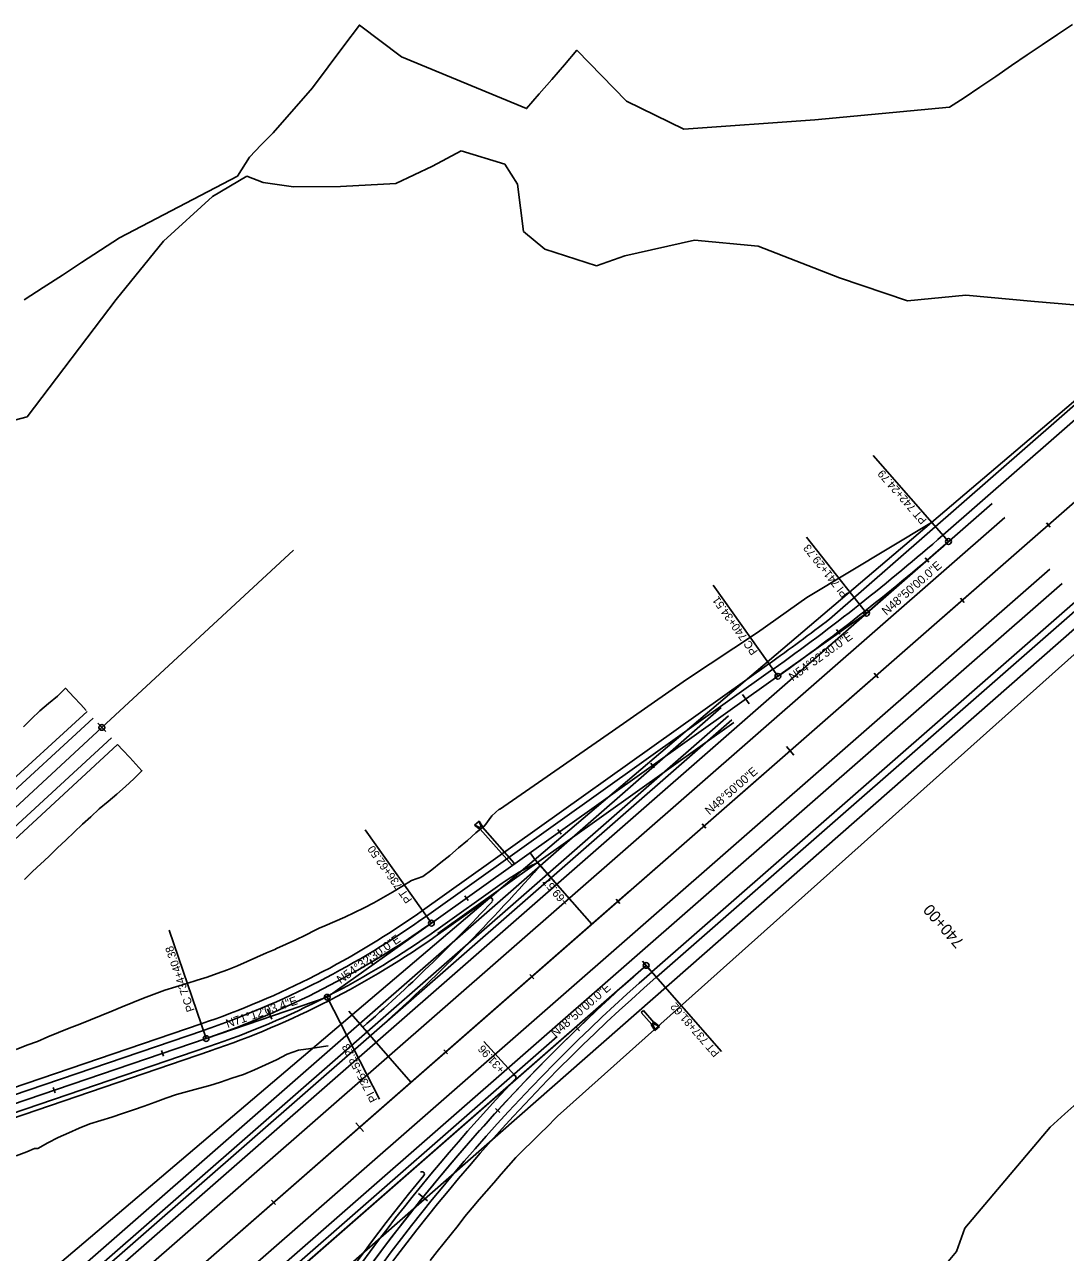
# Model space of a CAD drawing. Extents: x 1300404 to 1323571, y 234004 to 252077.
# Drawn here: x 1311522 to 1312432, y 241789 to 242863 of the extents above; entities that cross this region are included whole.
import ezdxf

# ---------------------------------------------------------------- set-up
doc = ezdxf.new("R2010")
doc.units = 0
for name, color, linetype in [('R_Const Limits', 7, 'Continuous'), ('R_Draft', 7, 'Continuous'), ('R_Flooplain', 7, 'Continuous'), ('R_Horz Alg Annot', 7, 'Continuous'), ('R_Horz Alg Annot Leader', 7, 'Continuous'), ('R_Horz Alg Major Ticks', 7, 'Continuous'), ('R_Horz Alg Minor Ticks', 7, 'Continuous'), ('R_Horz Alg Station Annot', 7, 'Continuous'), ('R_Horz Alg Tangents', 7, 'Continuous'), ('R_Horz Alg Tangents Text', 7, 'Continuous'), ('R_Information', 7, 'Continuous'), ('R_Lane Edge', 7, 'Continuous'), ('R_Pipe Culvert', 7, 'Continuous'), ('R_Proposed', 7, 'Continuous'), ('R_Shoulder', 7, 'Continuous')]:
    doc.layers.add(name, color=color, linetype=linetype)

msp = doc.modelspace()

# ---------------------------------------------------------------- linework, layer by layer
at = {"layer": 'R_Const Limits'}
for points in [[(1312438.5, 242863.3), (1312425.3, 242854.5), (1312412.1, 242845.7), (1312398.9, 242836.9), (1312385.2, 242827.4), (1312371.4, 242818), (1312357.6, 242808.6), (1312343.9, 242799.2), (1312331, 242791), (1312213.2, 242780), (1312098.6, 242771.9), (1312048.4, 242796.3), (1312005.2, 242840.8), (1311994.2, 242828.1), (1311983.2, 242815.4), (1311972.2, 242802.6), (1311961.2, 242789.9), (1311851.8, 242835.1), (1311814.9, 242862.8), (1311801.3, 242844.6), (1311787.6, 242826.3), (1311773.9, 242808), (1311739.5, 242768.5), (1311729.1, 242758), (1311718.8, 242747.4), (1311708.3, 242730.7), (1311605.1, 242676.9), (1311588.4, 242666), (1311571.8, 242655.1), (1311555.2, 242644.2), (1311538.5, 242633.4), (1311521.9, 242622.5)], [(1311514.8, 241966.8), (1311524, 241970.6), (1311533.4, 241973.9), (1311542.6, 241977.9), (1311551.9, 241981.8), (1311561.2, 241985.5), (1311570.5, 241989.1), (1311579.8, 241992.8), (1311589.1, 241996.6), (1311598.4, 242000.3), (1311607.6, 242004.2), (1311616.9, 242008.1), (1311626.2, 242011.7), (1311635.6, 242015.2), (1311644.9, 242018.9), (1311654.5, 242021.8), (1311664.1, 242024.6), (1311673, 242027.4), (1311681.9, 242030.3), (1311690.7, 242033.4), (1311699.5, 242036.7), (1311708.2, 242040.2), (1311716.7, 242043.8), (1311725.3, 242047.7), (1311733.8, 242051.5), (1311741.1, 242054.5), (1311742.4, 242055.1), (1311751, 242058.9), (1311759.4, 242062.9), (1311767.8, 242067), (1311776.2, 242071.2), (1311779.8, 242073.1), (1311784.8, 242075.1), (1311793.5, 242078.8), (1311802.1, 242082.6), (1311810.7, 242086.7), (1311819.1, 242090.9), (1311827.5, 242095.3), (1311835.8, 242099.9), (1311844, 242104.6), (1311852.1, 242109.5), (1311860.6, 242114.7), (1311870.4, 242118.2), (1311878.4, 242124.1), (1311886.2, 242130.4), (1311894, 242136.7), (1311901.7, 242143.2), (1311909.4, 242149.6), (1311916.8, 242156.3), (1311924.6, 242162.7), (1311930.8, 242171.3), (1311937.2, 242177.2), (1311937.4, 242176.9), (1311971.5, 242200.5), (1312036.2, 242245.4), (1312100.9, 242290.4), (1312163, 242331.7), (1312206.3, 242362.3), (1312315.2, 242427.9), (1312325.2, 242416.8)], [(1312524.9, 242388.2), (1311988.1, 241908.5), (1311986.5, 241906.8), (1311979.6, 241899.9), (1311972.6, 241893.1), (1311965.7, 241886.2), (1311958.7, 241879.3), (1311951.8, 241872.4), (1311945.3, 241865.2), (1311938.9, 241857.8), (1311932.5, 241850.4), (1311926.1, 241843.1), (1311919.7, 241835.7), (1311913.4, 241828.3), (1311907.2, 241820.7), (1311901.3, 241812.9), (1311895.1, 241805.4), (1311889, 241797.7), (1311882.9, 241790.1), (1311876.9, 241782.5)], [(1311521.1, 242249.1), (1311528.1, 242256.2), (1311535.4, 242263.1), (1311543.2, 242269.4), (1311550.9, 242275.8), (1311558, 242282.9), (1311565.3, 242275), (1311571.2, 242268.6), (1311576.1, 242263.3)], [(1311603.5, 242233.7), (1311608.2, 242228.6), (1311614.2, 242222.2), (1311624.8, 242210.7), (1311617.6, 242203.7), (1311610.3, 242196.9), (1311602.8, 242190.3), (1311595.3, 242183.7), (1311587.4, 242177.5), (1311580.2, 242170.5), (1311572.7, 242163.9), (1311565.4, 242157.1), (1311558.2, 242150.1), (1311551, 242143.2), (1311543.9, 242136.2), (1311539.2, 242131.8), (1311536.5, 242129.4), (1311529.1, 242122.7), (1311522, 242115.7)], [(1311787.6, 241970.2), (1311783.4, 241969.5), (1311781.7, 241969.3), (1311772.5, 241967.8), (1311761.6, 241966.3), (1311751.7, 241962.8), (1311742.4, 241957.9), (1311732.8, 241953.4), (1311723.2, 241949.1), (1311713.5, 241945.1), (1311703.5, 241941.7), (1311693.6, 241938.4), (1311684, 241935.4), (1311674.3, 241932.8), (1311664.6, 241930.3), (1311655, 241927.6), (1311645.6, 241924.3), (1311636.2, 241920.8), (1311626.8, 241917.4), (1311617.3, 241914.1), (1311607.8, 241910.9), (1311598.3, 241907.8), (1311588.8, 241904.7), (1311579.3, 241901.8), (1311570, 241898.1), (1311560.8, 241894), (1311551.6, 241890), (1311542.6, 241885.3), (1311533.7, 241880.4), (1311530.7, 241880.2), (1311524.2, 241877.5), (1311514.8, 241874)], [(1312326.8, 241777.9), (1312337.2, 241790.1), (1312344.5, 241810.6), (1312419, 241898.9), (1312431.9, 241910.7), (1312444.9, 241922.4)]]:
    msp.add_lwpolyline(points, dxfattribs=at)
at = {"layer": 'R_Draft'}
for p, q in [((1308397, 238971.9), (1312368.4, 242444.5)), ((1308407.8, 238959.5), (1312379.2, 242432.1)), ((1308447.3, 238914.3), (1312418.7, 242386.9)), ((1308458.2, 238901.9), (1312429.6, 242374.5)), ((1309184.5, 239689.1), (1312131.4, 242265.9)), ((1309037.8, 239548.2), (1312137.6, 242258.7)), ((1309193.7, 239678.5), (1312140.6, 242255.3)), ((1311883.5, 242068.5), (1312142.3, 242252.9)), ((1311968.7, 242132.9), (1311964.4, 242139)), ((1311968.7, 242132.9), (1312018.1, 242076.5)), ((1309413.9, 239721.6), (1312065.7, 242040.4)), ((1311805.7, 242000.4), (1311860, 241938.3)), ((1309410.9, 239725), (1311988, 241978.4)), ((1309410.9, 239725), (1311988, 241978.4))]:
    msp.add_line(p, q, dxfattribs=at)
at = {"layer": 'R_Flooplain'}
for p, q in [((1311903.9, 242752.8), (1311879, 242739.5)), ((1311942, 242741.2), (1311903.9, 242752.8)), ((1311879, 242739.5), (1311846.8, 242724.2)), ((1311953.2, 242723.7), (1311942, 242741.2)), ((1311716.5, 242730.7), (1311686.6, 242712.9)), ((1311730.7, 242725.2), (1311716.5, 242730.7)), ((1311757.2, 242721.4), (1311730.7, 242725.2)), ((1311798.3, 242721.8), (1311757.2, 242721.4)), ((1311846.8, 242724.2), (1311798.3, 242721.8)), ((1311958.4, 242682.3), (1311953.2, 242723.7)), ((1311686.6, 242712.9), (1311643.5, 242673.9)), ((1311977, 242666.8), (1311958.4, 242682.3)), ((1311643.5, 242673.9), (1311602.2, 242622.8)), ((1312108.1, 242674.7), (1312046.9, 242660.9)), ((1312163.5, 242669.5), (1312108.1, 242674.7)), ((1312022.3, 242652.4), (1311977, 242666.8)), ((1312046.9, 242660.9), (1312022.3, 242652.4)), ((1312234.7, 242641.7), (1312163.5, 242669.5)), ((1312294.2, 242621.8), (1312234.7, 242641.7)), ((1311602.2, 242622.8), (1311524.5, 242520.2)), ((1312345.2, 242626.5), (1312294.2, 242621.8)), ((1312405.4, 242621), (1312345.2, 242626.5)), ((1312475.3, 242615.1), (1312405.4, 242621)), ((1311459.5, 241700.8), (1312470.1, 242559.7)), ((1311524.5, 242520.2), (1311431.4, 242495.9)), ((1312629.3, 242500.9), (1311599.5, 241597))]:
    msp.add_line(p, q, dxfattribs=at)
at = {"layer": 'R_Horz Alg Annot Leader'}
for p, q in [((1312000.7, 242096.3), (1311971.9, 242129.3)), ((1311951.2, 241943.9), (1311923.7, 241973.9))]:
    msp.add_line(p, q, dxfattribs=at)
for points in [[(1312330.1, 242411.2), (1312264.3, 242486.4)], [(1312206, 242414.9), (1312258.5, 242348.5)], [(1312180.9, 242293.3), (1312124.2, 242372.9)], [(1311877.9, 242077.4), (1311819.9, 242158.9)], [(1311680.9, 241976.5), (1311648.7, 242071.2)], [(1312065.7, 242040.4), (1312131.5, 241965.1)], [(1311786.8, 242012.6), (1311832.4, 241923.6)]]:
    msp.add_lwpolyline(points, dxfattribs=at)
at = {"layer": 'R_Horz Alg Major Ticks'}
for points in [[(1312149.9, 242277.3), (1312155.7, 242269.2)], [(1311586.3, 242252.3), (1311593.1, 242244.9)], [(1312188.3, 242231.9), (1312194.9, 242224.4)], [(1312062.4, 242044.1), (1312069, 242036.6)], [(1311734.6, 242002.5), (1311738.5, 241993.3)], [(1311811.9, 241902.8), (1311818.5, 241895.3)], [(1311866.7, 241840.9), (1311874.5, 241834.6)]]:
    msp.add_lwpolyline(points, dxfattribs=at)
at = {"layer": 'R_Horz Alg Minor Ticks'}
for points in [[(1312415.8, 242427.5), (1312419, 242423.8)], [(1312309.8, 242396.9), (1312313, 242393.1)], [(1312340.5, 242361.7), (1312343.8, 242357.9)], [(1312232.1, 242334.1), (1312235.1, 242330.2)], [(1312265.2, 242295.9), (1312268.5, 242292.1)], [(1311588, 242250.4), (1311591.4, 242246.8)], [(1312069.9, 242217.3), (1312072.8, 242213.2)], [(1311988.4, 242159.2), (1311991.3, 242155.2)], [(1312114.6, 242164.2), (1312117.9, 242160.5)], [(1311907, 242101.2), (1311909.9, 242097.2)], [(1312039.4, 242098.4), (1312042.6, 242094.6)], [(1311824.3, 242045.5), (1311826.8, 242041.2)], [(1311964.1, 242032.6), (1311967.4, 242028.8)], [(1312003.9, 241986.9), (1312007.3, 241983.3)], [(1311641.9, 241965.9), (1311643.5, 241961.1)], [(1311888.8, 241966.7), (1311892.1, 241963)], [(1311547.2, 241933.6), (1311548.8, 241928.9)], [(1311934, 241915.2), (1311937.7, 241911.8)], [(1311738.2, 241835.1), (1311741.5, 241831.3)]]:
    msp.add_lwpolyline(points, dxfattribs=at)
at = {"layer": 'R_Horz Alg Tangents'}
for p, q in [((1312258.5, 242348.5), (1312330.1, 242411.2)), ((1312180.9, 242293.3), (1312258.5, 242348.5)), ((1311786.8, 242012.6), (1311877.9, 242077.4)), ((1311703.8, 241724), (1312065.7, 242040.4)), ((1311680.9, 241976.5), (1311786.8, 242012.6))]:
    msp.add_line(p, q, dxfattribs=at)
at = {"layer": 'R_Information'}
msp.add_line((1311589.7, 242248.6), (1311757.3, 242403.7), dxfattribs=at)
at = {"layer": 'R_Lane Edge'}
for p, q in [((1312325.2, 242416.8), (1312532.4, 242598)), ((1312070.6, 242034.7), (1312484.9, 242397)), ((1312176.6, 242299.4), (1311873.5, 242083.6)), ((1311434.8, 242121.5), (1311582.2, 242256.7)), ((1311451.1, 242103.9), (1311598.1, 242239.6)), ((1311881.7, 242071), (1311939.8, 242112.3)), ((1310713.2, 241655), (1311678.5, 241983.6)), ((1310718, 241640.8), (1311683.3, 241969.4))]:
    msp.add_line(p, q, dxfattribs=at)
for centre, radius, start, end in [((1311073, 243848.9), 1902.4, 305.4583, 311.1667), ((1310780.8, 243167.8), 1582, 311.2779, 318.8448), ((1312064.3, 241934), 217.5, 115.9157, 124.919), ((1311970.4, 242128), 2, 319.6969, 125.4583), ((1311434.7, 242699.7), 756.4, 288.7991, 305.4583), ((1311434.7, 242699.7), 771.4, 288.7991, 305.4583), ((1313143.2, 240808), 1629.5, 131.1667, 163.8918), ((1313143.2, 240808), 1644.5, 136.4518, 163.8918), ((1311949.9, 241942.4), 2, 316.4518, 131.1667)]:
    msp.add_arc(centre, radius, start, end, dxfattribs=at)
at = {"layer": 'R_Pipe Culvert'}
for p, q in [((1311915.6, 242163), (1311919.7, 242166.7)), ((1311922.5, 242161.3), (1311919.5, 242166.5)), ((1311919.5, 242166.5), (1311921, 242162.8)), ((1311922.9, 242161.3), (1311919.7, 242166.7)), ((1311921, 242162.8), (1311919.7, 242166.7)), ((1311920.6, 242159.2), (1311915.6, 242163)), ((1311919.3, 242161.3), (1311915.6, 242163)), ((1311920.6, 242159.6), (1311915.8, 242163.2)), ((1311915.8, 242163.2), (1311919.3, 242161.3)), ((1311920.6, 242159.2), (1311922.9, 242161.3)), ((1311920.6, 242159.6), (1311922.5, 242161.3)), ((1311920.6, 242159.6), (1311920.6, 242159.2)), ((1311920.6, 242159.6), (1311948.4, 242128.1)), ((1311922.5, 242161.3), (1311922.9, 242161.3)), ((1311950.3, 242129.8), (1311922.5, 242161.3)), ((1311950.3, 242129.8), (1311948.4, 242128.1)), ((1312061.4, 241999.4), (1312063.3, 242001)), ((1312070.6, 241988.8), (1312061.4, 241999.4)), ((1312072.5, 241990.5), (1312063.3, 242001)), ((1312072.6, 241990.9), (1312070.2, 241988.9)), ((1312070.2, 241988.9), (1312073.3, 241983.4)), ((1312070.6, 241988.8), (1312070.2, 241988.9)), ((1312072.5, 241990.5), (1312070.6, 241988.8)), ((1312070.6, 241988.8), (1312073.5, 241983.6)), ((1312072.1, 241987.3), (1312073.3, 241983.4)), ((1312073.5, 241983.6), (1312072.1, 241987.3)), ((1312072.5, 241990.5), (1312072.6, 241990.9)), ((1312072.5, 241990.5), (1312077.3, 241986.9)), ((1312072.6, 241990.9), (1312077.5, 241987.1)), ((1312077.5, 241987.1), (1312073.3, 241983.4)), ((1312073.8, 241988.8), (1312077.5, 241987.1)), ((1312077.3, 241986.9), (1312073.8, 241988.8))]:
    msp.add_line(p, q, dxfattribs=at)
for centre, start, end in [((1311919.8, 242162.4), 245.071, 17.7054), ((1312073.3, 241987.7), 64.75, 197.3844)]:
    msp.add_arc(centre, 1.25, start, end, dxfattribs=at)
at = {"layer": 'R_Proposed'}
for p, q in [((1308463.1, 238968), (1312793.8, 242754.8)), ((1308427.6, 238936.9), (1312399, 242409.5)), ((1309180.4, 239595.2), (1312399, 242409.5)), ((1309180.4, 239595.2), (1312399, 242409.5)), ((1311877.9, 242077.4), (1312180.9, 242293.3)), ((1311366.7, 242042.1), (1311589.7, 242248.6)), ((1309180.4, 239595.2), (1312051.5, 242105.7)), ((1310715.6, 241647.9), (1311680.9, 241976.5))]:
    msp.add_line(p, q, dxfattribs=at)
for centre in [(1312330.1, 242411.2), (1312258.5, 242348.5), (1312180.9, 242293.3), (1311589.7, 242248.6), (1311877.9, 242077.4), (1312065.7, 242040.4), (1311786.8, 242012.6), (1311680.9, 241976.5)]:
    msp.add_circle(centre, 2.5, dxfattribs=at)
for centre, radius, start, end in [((1311073, 243848.9), 1909.9, 305.4583, 311.1667), ((1311434.7, 242699.7), 763.9, 288.7991, 305.4583), ((1313143.2, 240808), 1637, 131.1667, 163.8918), ((1313143.2, 240808), 1637, 131.1667, 163.8918), ((1313143.2, 240808), 1637, 131.1667, 163.0419)]:
    msp.add_arc(centre, radius, start, end, dxfattribs=at)
at = {"layer": 'R_Shoulder'}
for p, q in [((1312226, 242343.3), (1312525.8, 242605.5)), ((1312074.6, 242030.2), (1312488.9, 242392.6)), ((1312173.1, 242304.2), (1311870.1, 242088.4)), ((1311429.4, 242127.4), (1311576.8, 242262.6)), ((1311456.5, 242098.1), (1311603.5, 242233.7)), ((1311884, 242067.7), (1311928.3, 242099.2)), ((1310711.2, 241660.7), (1311676.5, 241989.3)), ((1310766.6, 241653.1), (1311684.6, 241965.6))]:
    msp.add_line(p, q, dxfattribs=at)
for centre, radius, start, end in [((1311073, 243848.9), 1896.4, 305.4583, 307.4611), ((1311073, 243848.9), 1896.4, 305.4583, 307.4611), ((1310780.5, 243167.5), 1572, 311.2928, 317.0394), ((1311929.4, 242097.6), 2, 317.0394, 125.4583), ((1311434.7, 242699.7), 750.4, 288.7991, 305.4583), ((1311434.7, 242699.7), 775.4, 288.7991, 305.4583), ((1313143.2, 240808), 1623.5, 131.1667, 163.8918), ((1313143.2, 240808), 1648.5, 140.4948, 163.8918), ((1311869.8, 241858), 2, 320.4948, 130.9731)]:
    msp.add_arc(centre, radius, start, end, dxfattribs=at)

# ---------------------------------------------------------------- texts
at = {"layer": 'R_Horz Alg Annot'}
for s, rotation, p in [('PT 742+24.79', 131.1667, (1312311.6, 242430.1)), ('PI 741+29.73', 128.3125, (1312242.7, 242365.6)), ('PC 740+34.51', 125.4583, (1312163.6, 242315)), ('PT 736+62.50', 125.4583, (1311861.5, 242097.9)), ('+69.57', 130.5769, (1311998.7, 242095.7)), ('PC 734+40.38', 108.7991, (1311670.9, 242001.2)), ('PT 737+81.62', 131.1667, (1312130.4, 241964.1)), ('PI 735+52.23', 117.1287, (1311831, 241922.9)), ('+31.96', 131.9423, (1311942.5, 241950))]:
    msp.add_text(s, height=7, rotation=rotation, dxfattribs=at).set_placement(p)
at = {"layer": 'R_Horz Alg Station Annot'}
msp.add_text('740+00', height=10, rotation=131.1667, dxfattribs=at).set_placement((1312344.3, 242061.1))
at = {"layer": 'R_Horz Alg Tangents Text'}
for s, rotation, p in [('N48%%d50\'00.0"E', 41.1667, (1312275.8, 242346.2)), ('N54%%d32\'30.0"E', 35.4583, (1312193.8, 242288.8)), ('N48%%d50\'00"E', 41.1667, (1312121.1, 242171.6)), ('N54%%d32\'30.0"E', 35.4583, (1311798.5, 242024)), ('N48%%d50\'00.0"E', 41.1667, (1311986.4, 241977.1)), ('N71%%d12\'03.4"E', 18.7991, (1311699.7, 241985.6))]:
    msp.add_text(s, height=7.5, rotation=rotation, dxfattribs=at).set_placement(p)

doc.saveas('drawing.dxf')
